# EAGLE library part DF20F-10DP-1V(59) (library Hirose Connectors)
CONN, VERT, SMT, 10 POS, 5x2, 1mm PITCH, GOLD (HIROSE)
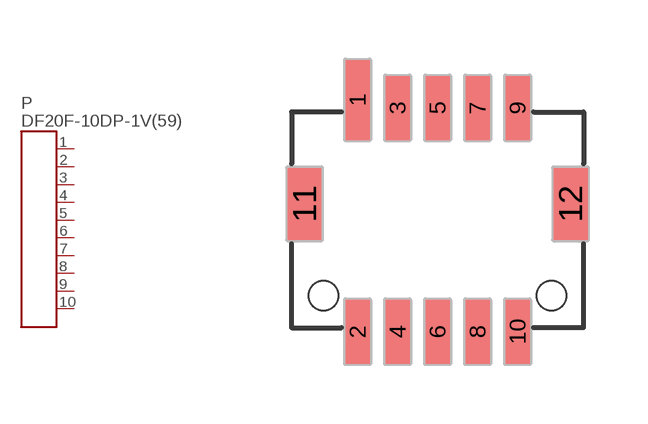
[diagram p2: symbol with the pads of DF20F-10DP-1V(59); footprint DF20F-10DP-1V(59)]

Designator prefix P

## DF20F-10DP-1V(59)  [DF20F-10DP-1V(59)]
1  P$1
2  P$2
3  P$3
4  P$4
5  P$5
6  P$6
7  P$7
8  P$8
9  P$9
10  P$10

## Footprint DF20F-10DP-1V(59) (pad centres in mm)
smd 0.6 x 2: 1 -2,3
smd 0.6 x 1.6: 2 -2,-2.8; 3 -1,2.8; 4 -1,-2.8; 5 0,2.8; 6 0,-2.8; 7 1,2.8; 8 1,-2.8; 9 2,2.8; 10 2,-2.8
smd 0.85 x 1.8: 11 -3.325,0.4; 12 3.325,0.4
hole 0.737 at -2.85,-1.9
hole 0.737 at 2.85,-1.9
